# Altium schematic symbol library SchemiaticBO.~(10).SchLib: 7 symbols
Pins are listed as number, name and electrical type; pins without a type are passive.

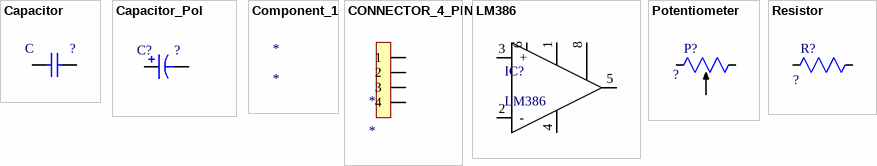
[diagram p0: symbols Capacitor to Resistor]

## Capacitor
designator C  (value not drawn)
footprint SMD_0603_BO
footprint SMD_1206_BO
pins: 1, 2

## Capacitor_Pol
designator C?  (value not drawn)
footprint Panasonic_K16_BO
footprint CAP_POL_s16x25 (Raster 7.5)
footprint CAP_POL_s10x20 (Raster 5)
footprint CAP_POL_s10x16 (Raster 5)
footprint CAP_POL_s6.3x11 (Raster 2.5)
footprint CAP_POL_s5x11 (Raster 2)
footprint CAP_POL_SMD_6.8x6.8x8
footprint PANASONIC_B_BO
footprint PANASONIC_C_BO
footprint PANASONIC_D8_BO
pins: 1, 2

## Component_1
designator *

## CONNECTOR_4_PIN
designator *
footprint Connector double
pins: 1, 2, 3, 4

## LM386
designator IC?
footprint SO8_BO
pins: 1, 2 -, 3 +, 4, 5, 6, 8

## Potentiometer
designator P?  (value not drawn)
footprint POT_1801-J_BO
pins: 1, 2, 3

## Resistor
designator R?  (value not drawn)
footprint RES (Raster 10mm)
footprint SMD_1206_BO
pins: 1 OUT, 2 OUT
